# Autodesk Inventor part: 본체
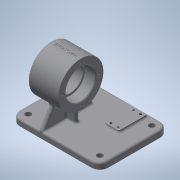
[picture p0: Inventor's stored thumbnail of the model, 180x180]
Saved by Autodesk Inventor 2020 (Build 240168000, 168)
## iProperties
Created: 2019-09
Part Number: 본체
Material: 알루미늄 6061
Document SubType Name: Modeling
Designer: mduedu
Density: 2.71 g/cm^3
Mass: 544.697 g
Surface Area: 497.052 cm^2
Volume: 200.995 cm^3
Appearance: 기본값
Author: mduedu
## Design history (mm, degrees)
sketch "스케치1"
  geometry: L1 (42, -62)-(-84, -62); L2 (-84, -62)-(-84, 36); L3 (-84, 36)-(42, 36); L4 (42, 36)-(42, -62); 1 further point
  constraints: 8 end point, 2 parallel, 1 horizontal, 1 perpendicular
  dimensions: "d0" = 36 distance from line of L3 point (0, 0); "d1" = 98 distance of L1.end L2.end; "d2" = 42 distance from line of L4 point (0, 0); "d3" = 126 distance of L2.end L3.end
extrude "돌출1" new body sketch "스케치1" distance "d4" = 9; taper "d5" = 0 deg
sketch "스케치2"
  geometry: L1 (0, -62)-(0, 36) reference; L2 (27, -32)-(91, -32); L3 (91, -32)-(91, 32); L4 (91, 32)-(27, 32); L5 (27, 32)-(27, -32); L6 (27, -32)-(91, 32); L7 (91, -32)-(27, 32); C1 r 32 at (59, 0); 3 further points
  constraints: 12 end point, 5 midpoint, 2 parallel, 1 centre point, 1 horizontal, 1 horizontal alignment, 1 perpendicular, 1 tangent
  dimensions: "d87" = 64 distance of L4.end L3.end; "d88" = 64 distance of L3.end L2.end; "d89" = 59 distance from line of point (59, 0) L1
extrude "돌출2" join sketch "스케치2" stored distance "d8" = 42; taper "d9" = 0 deg
node "작업 평면1"
sketch "스케치12"
  geometry: L1 (62, -50)-(-36, -50) reference; L2 (-21.048, -24.103)-(-36, -50); L3 (21.048, -24.103)-(36, -50); L4 (0, 0)-(0, -59); L5 (-36, -59)-(-36, -50) reference; L6 (-36, -50)-(36, -50); A1 r 32 centre (0, 0) between (-21.048, -24.103) and (21.048, -24.103) reference
  constraints: 8 end point, 2 point on circle, 2 symmetric about line, 1 perpendicular, 1 point on line
  dimensions: "d98" = 30 deg angle of L5 L2
extrude "돌출6" join sketch "스케치12" stored distance "d99" = 6; taper "d100" = 0 deg
node "작업 평면2"
  node "작업축1"
sketch "스케치13"
  geometry: L1 (-21, -32)-(21, -32) reference; L2 (84, -50)-(-42, -50) reference; L3 (0, -32)-(0, -59); L4 (-42, -59)-(-42, -50) reference; L5 (-16, -32)-(-16, -50); L6 (16, -32)-(16, -50)
  constraints: 6 end point, 4 point on line, 2 perpendicular, 1 midpoint, 1 parallel, 1 symmetric about line
  dimensions: "d130" = 26 distance between parallel lines of L4 L5
feature "리브3" dims "d133" = 1, "d134" = 6, "d135" = 0, "d136" = 0, "d137" = 1, "d138" = 1
feature "리브4" dims "d139" = 1, "d140" = 6, "d141" = 0, "d142" = 0, "d143" = 1, "d144" = 1
sketch "스케치14"
  geometry: L1 (-21, 32)-(-21, -32) reference; L2 (21, -32)-(21, 32) reference; L3 (-21, 0)-(21, 0); L4 (21, 0)-(21, -21); L5 (21, -21)-(6, -21); L6 (6, -21)-(6, -18); L7 (6, -18)-(-6, -18); L8 (-6, -18)-(-6, -21); L9 (-6, -21)-(-21, -21); L10 (-21, 0)-(-21, -21); 1 further point
  constraints: 16 end point, 2 midpoint, 2 parallel, 2 perpendicular, 1 collinear, 1 horizontal, 1 point on line, 1 vertical
  dimensions: "d115" = 15 distance of L8.end L9.end; "d119" = 15 distance of L4.end L5.end; "d120" = 42 diameter of L9 L3; "d121" = 36 diameter of L7 L3; "d122" = 42 diameter of L5 L3
revolve "회전1" sketch "스케치14" stored, may be unused: angle "d123" = 90 deg
fillet "모깎기1" dims "d29" = 0.3
chamfer "모따기1" distance "d30" = 1; stored, may be unused: second distance "d31" = 2, angle "d32" = 45 deg
sketch "스케치11"
  geometry: C1 r 22 at (0, 59); C2 r 22 at (0, 59) reference; A1 r 26 centre (0, 59) between (0, 85) and (26, 59); 3 further points
  constraints: 4 point on circle, 2 centre point, 2 horizontal alignment, 2 vertical alignment, 1 coincident
  dimensions: "d124" = 52 diameter of A1
hole "구멍6" sketch "스케치11" at (0, 85), (26, 59), (0, 33), (-26, 59) diameter "d91" = 3.242; stored, may be unused: countersink angle "d95" = 90 deg, drill point angle "d97" = 118 deg; dims "d92" = 8, "d93" = 4, "d94" = 2, "d96" = 10
fillet "모깎기2" dims "d44" = 12
sketch "스케치6"
  geometry: L1 (-42, 50)-(-42, -24) reference; L2 (-30, -36)-(-3, -36) reference; L3 (84, -24)-(84, 50) reference; L4 (72, 62)-(-30, 62) reference; L5 (-3, 3)-(-3, 36) reference; L6 (-3, 36)-(3, 36) reference; L7 (3, 36)-(3, 3) reference; L8 (3, -36)-(72, -36) reference; L9 (-3, -36)-(-3, -3) reference; L10 (-3, -3)-(-16, -3) reference; L11 (-16, -3)-(-16, 3) reference; L12 (-16, 3)-(-3, 3) reference; L13 (3, 3)-(16, 3) reference; L14 (16, 3)-(16, -3) reference; L15 (16, -3)-(3, -3) reference; L16 (3, -3)-(3, -36) reference; A1 r 12 centre (-30, 50) between (-30, 62) and (-42, 50) reference; A2 r 12 centre (-30, -24) between (-42, -24) and (-30, -36) reference; A3 r 12 centre (72, -24) between (72, -36) and (84, -24) reference; A4 r 12 centre (72, 50) between (84, 50) and (72, 62) reference; 5 further points
  constraints: 4 coincident
hole "구멍3" sketch "스케치6" at (-30, 50), (72, 50), (72, -24), (-30, -24) diameter "d45" = 8; stored, may be unused: countersink angle "d49" = 90 deg, drill point angle "d51" = 118 deg; dims "d46" = 8, "d47" = 4, "d48" = 2, "d50" = 10
sketch "스케치7"
  geometry: L1 (38, 57)-(58, 57); L2 (58, 57)-(58, 17); L3 (58, 17)-(38, 17); L4 (38, 17)-(38, 57); L5 (72, 62)-(-30, 62) reference; 3 further points
  constraints: 8 end point, 2 midpoint, 2 parallel, 1 horizontal, 1 perpendicular
  dimensions: "d52" = 48 horizontal distance of point (48, 57) point (0, 0); "d53" = 20 distance of L1.start L1.end; "d54" = 40 distance of L1.end L2.end; "d55" = 25 distance from line of point (38, 37) L5
extrude "돌출5" join sketch "스케치7" distance "d56" = 3; taper "d57" = 0 deg
fillet "모깎기12" dims "d128" = 3
fillet "모깎기10" dims "d126" = 3
fillet "모깎기14" dims "d145" = 3
fillet "모깎기3" dims "d58" = 3
fillet "모깎기4" dims "d59" = 3
fillet "모깎기5" dims "d60" = 3
fillet "모깎기15" dims "d146" = 3
sketch "스케치8"
  geometry: L1 (72, 62)-(58.317, 62) reference; L2 (84, -24)-(84, 50) reference; C1 r 1.5 at (43, 53); C2 r 1.5 at (53, 21); 1 further point
  constraints: 2 centre point, 1 equal radius
  dimensions: "d64" = 3 diameter of C1; "d65" = 9 distance from line of C1.centre L1; "d66" = 32 vertical distance of C2.centre C1.centre; "d67" = 10 horizontal distance of C2.centre C1.centre; "d68" = 31 distance from line of L2 C2.centre
hole "구멍4" sketch "스케치8" at (43, 53), (53, 21) diameter "d69" = 3; stored, may be unused: countersink angle "d73" = 90 deg, drill point angle "d75" = 118 deg; dims "d70" = 8, "d71" = 4, "d72" = 2, "d74" = 6
sketch "스케치9"
  geometry: C1 r 1.5 at (43, 53) reference; C2 r 1.5 at (53, 21) reference; 3 further points
  constraints: 2 horizontal alignment, 2 vertical alignment
hole "구멍5" sketch "스케치9" at (53, 53), (43, 21) diameter "d76" = 3.242; stored, may be unused: countersink angle "d80" = 90 deg, drill point angle "d82" = 118 deg; dims "d77" = 6, "d78" = 4, "d79" = 2, "d81" = 8
node "작업 평면3"
sketch "스케치10"
  geometry: 3 further points
  constraints: 2 coincident, 1 other
feature "엠보싱1" sketch "스케치10" dims "d0" = 36, "d1" = 98, "d2" = 42, "d3" = 126, "d85" = 0.5, "d86" = 0
node "솔리드1"
mirror "대칭2"
node "투영된 루프1"
other parameters: "d101" = 90 deg
